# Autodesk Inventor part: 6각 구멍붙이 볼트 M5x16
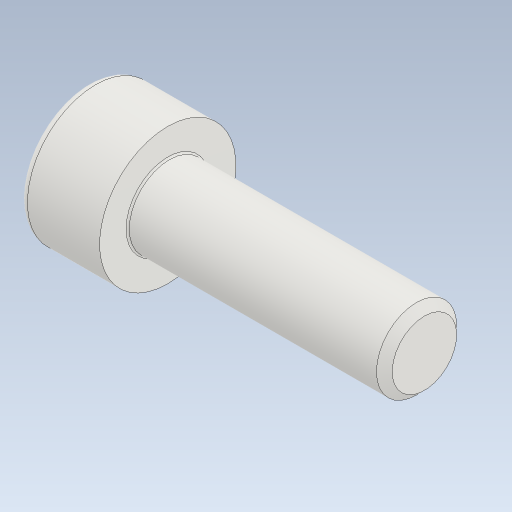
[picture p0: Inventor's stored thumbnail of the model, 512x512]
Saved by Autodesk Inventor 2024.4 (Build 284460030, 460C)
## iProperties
Created: 2026-09
Part Number: 6각 구멍붙이 볼트 M5x16
Material: 강철, 연강
Description: 6각머리 태핑 나사
Document SubType Name: Modeling
Designer: user
Density: 7.85 g/cm^3
Appearance: 기본값
Author: jhkim
Sending System: Autodesk Inventor 2027
Preprocessor: ST-DEVELOPER v20.1
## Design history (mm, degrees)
feature "Solid1"
node "솔리드1"
